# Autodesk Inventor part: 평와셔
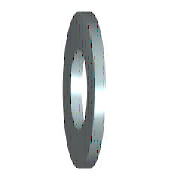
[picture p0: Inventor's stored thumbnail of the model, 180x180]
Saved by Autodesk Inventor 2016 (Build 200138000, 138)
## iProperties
IsCustomPart: 1
Created: 2012-02
Part Number: 평와셔
Material: 강철
Description: 평면 와셔 - 초대형 시리즈 - 제품 등급 C
Document SubType Name: Modeling
Standard: ISO 7094
Designer: mduedu
Standard Revision: Second edition 2000-06-01
Standards Organization: ISO
Language: ko-KR
Size Designation: ST 5 - 100 HV
Categories: <MemberInstance><Categories><Category DisplayName="조임쇠" InternalName="e4da775c-781d-43d5-af7c-5136215cf5a6" Mnemonic="FSTN"><Category DisplayName="와셔" InternalN
Density: 7.85 g/cm^3
Appearance: 강철
Mass: 3.62216 g
Surface Area: 6.09076 cm^2
Volume: 0.461421 cm^3
Author: mduedu
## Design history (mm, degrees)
sketch "스케치"
  geometry: C1 r 9 at (0, 0); C2 r 2.75 at (0, 0); 1 further point
  constraints: 2 centre point, 2 coincident
  dimensions: "d0" = 5.5 diameter of C2 (= SD1); "d1" = 18 diameter of C1 (= SD2)
extrude "본체" new body sketch "스케치" distance "d2" = 2 (= SD); taper "d3" = 0 deg
workaxis "Work Axis1"
workplane "Work Plane1"
body "Solid1"
other parameters: "SD1" = 5.5 [user parameter; used in 1 equation term], "SD2" = 18 [user parameter; used in 1 equation term], "SD" = 2 [user parameter; used in 1 equation term], "d4" = 0, "d5" = 0, "d6" = 0, "d7" = 0, "NND" = 5 [user parameter]
